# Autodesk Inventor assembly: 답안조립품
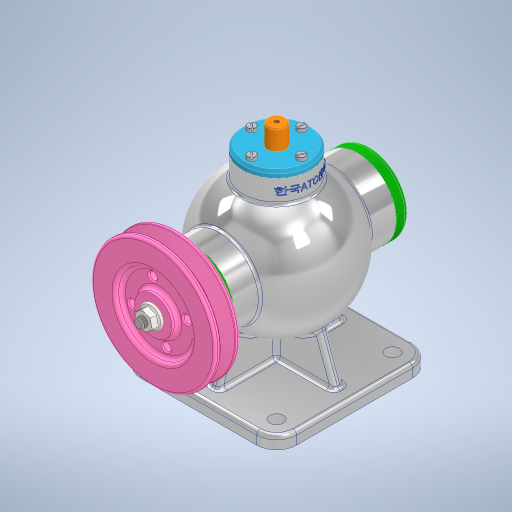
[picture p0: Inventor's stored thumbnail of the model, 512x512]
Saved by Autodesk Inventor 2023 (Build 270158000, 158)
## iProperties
Created: 2023-07
Part Number: 답안조립품
Document SubType Name: Assembly
Designer: Owner
Author: Owner
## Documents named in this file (16)
- C:\Users\Owner\Desktop\730711V1009\답안조립품.iam
- C:\Users\Owner\Desktop\730711V1009\본체.ipt
- C:\Users\Owner\Desktop\730711V1009\뒤커버.ipt
- C:\Users\Owner\Desktop\730711V1009\앞커버.ipt
- C:\Users\Owner\Desktop\730711V1009\상부커버.ipt
- C:\Users\Owner\Desktop\730711V1009\베어링- 6202.ipt
- KS B 2023 - 6202 - 15 x 35 x 11 - 7.8.ipt
- C:\Users\Owner\Desktop\730711V1009\칼라.ipt
- C:\Users\Owner\Desktop\730711V1009\편심축.ipt
- C:\Users\Owner\Desktop\730711V1009\키 4 x 4 x 12.ipt
- C:\Users\Owner\Desktop\730711V1009\오일실 15 30 7.ipt
- C:\Users\Owner\Desktop\730711V1009\V-벨트풀리.ipt
- C:\Users\Owner\Desktop\730711V1009\너트 M8.ipt
- C:\Users\Owner\Desktop\730711V1009\볼트 M4 x 16.ipt
- C:\Users\Owner\Desktop\730711V1009\볼트 M4 x 12.ipt
- C:\Users\Owner\Desktop\730711V1009\슬라이드.ipt
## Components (15 placed, 4 different names)
1. KS B 2023 - 6202 - 15 x 35 x 11 - 7.8:1
2. KS B 2023 - 6202 - 15 x 35 x 11 - 7.8:2
3. V-벨트풀리:1
4. ISO 4762 M4 x 16:1
5. ISO 4762 M4 x 16:2
6. ISO 4762 M4 x 16:3
7. ISO 4762 M4 x 16:4
8. ISO 4762 M4 x 16:5
9. ISO 4762 M4 x 16:6
10. ISO 4762 M4 x 16:7
11. ISO 4762 M4 x 16:8
12. KS B 1021 - 에 따름 ISO 1207 - 미터 A  M 4 x 12:1
13. KS B 1021 - 에 따름 ISO 1207 - 미터 A  M 4 x 12:2
14. KS B 1021 - 에 따름 ISO 1207 - 미터 A  M 4 x 12:3
15. KS B 1021 - 에 따름 ISO 1207 - 미터 A  M 4 x 12:4
